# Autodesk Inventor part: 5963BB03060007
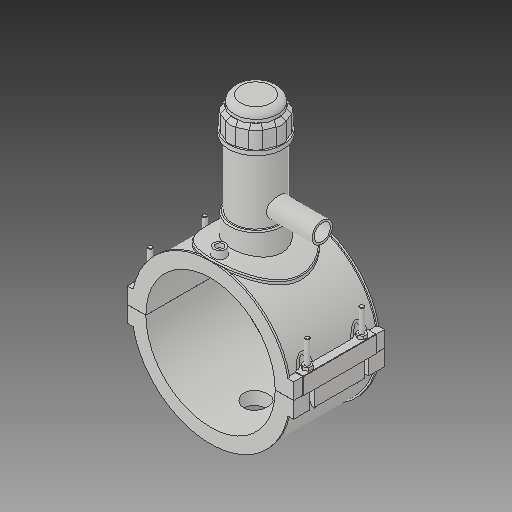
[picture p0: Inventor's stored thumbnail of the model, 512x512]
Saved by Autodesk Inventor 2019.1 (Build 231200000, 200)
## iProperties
Created: 2017-07
Part Number: 5963BB03060007
Material: Generic
Description: PLASSON TAPPING SADDLE 6''IPS x 1 3/4''IPS
Document SubType Name: Modeling
Designer: KIM
Mass: 1712.7 g
Surface Area: 2671.49 cm^2
Volume: 1712.7 cm^3
Density: 1 g/cm^3
Appearance: Default
Author: KIM
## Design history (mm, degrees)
derived "5963B.ipt"
feature "Solid1::5963B.ipt"
feature "Solid2::5963B.ipt"
feature "Solid4::5963B.ipt"
feature "Solid5::5963B.ipt"
tag "TaggingFeature1"
body "Solid1"
body "Solid2"
other parameters: "d0" = 168, "d2" = 215.9, "d3" = 42, "d4" = 118.11, "d5" = 0, "d6" = 0.1, "d8" = 0, "d19" = 6, "d20" = 6, "d21" = 70.866, "d23" = 0, "d24" = 35.433, "d26" = 0, "d29" = 3, "d30" = 56, "d31" = 6, "d32" = 0, "d33" = 0, "d34" = 0.6, "d40" = 104.832, "d41" = 117.6, "d43" = 0, "d45" = 0, "d47" = 171.666, "d70" = 15, "d72" = 0, "d73" = 6, "d75" = 5, "d76" = 0, "d77" = 8.4, "d78" = 114, "d79" = 15, "d80" = 47.244, "d82" = 5 deg, "d84" = 4, "d85" = 14, "d86" = 0, "d87" = 3, "d88" = 0, "d89" = 1, "d90" = 1, "d91" = 94.488, "d92" = 0, "d93" = 0.5, "d94" = 88.42105, "d96" = 205.632, "d97" = 2.3622, "d98" = 0, "d102" = 1.68, "d120" = 140 deg, "d121" = 24.228, "d122" = 20 deg, "d123" = 403.2, "d124" = 120.96, "d126" = 0, "d143" = 173.04, "d145" = 25.84615, "d149" = 2.52, "d150" = 28.43077, "d153" = 118.11, "d154" = 0, "d156" = 100.8, "d157" = 160 deg, "d159" = 6.72, "d161" = 2.52, "d162" = 70.866, "d163" = 0, "d164" = 84, "d167" = 16.8, "d168" = 98.34146, "d170" = 3.2805, "d172" = 0, "d173" = 1, "d175" = 84, "d176" = 20 deg, "d177" = 11.76, "d178" = 33.6, "d180" = 0, "d183" = 13.44, "d184" = 9.408, "d185" = 38.38575, "d186" = 38.38575, "d187" = 100.8, "d188" = 10.08, "d189" = 11.76, "d190" = 0, "d191" = 151.2, "d193" = 6.1236, "d194" = 4.13385, "d195" = 90 deg, "d197" = 0, "d199" = 0, "d200" = 16.8, "d202" = 0, "d203" = 177.038, "d204" = 67.032, "d205" = 49.392, "d206" = 59.976, "d207" = 132.7785, "d208" = 138.08964, "d209" = 164.64534, "d210" = 60.6816, "d211" = 70.56, "d212" = 56.448, "d213" = 46.5516, "d216" = 0, "d217" = 16.8, "d218" = 8.4, "d219" = 1.68, "d222" = 168, "d224" = 0, "d230" = 5.04, "d233" = 6, "d236" = 107.95, "d237" = 35.433, "d238" = 6.02433, "d240" = 35.433, "d241" = 35.433, "d242" = 35.433, "d243" = 6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
